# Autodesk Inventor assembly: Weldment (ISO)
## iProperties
Length Units: 11269
Angle Units: 11283
Time Units: 11279
Mass Units: 11290
Length Display Precision: 3
Angle Display Precision: 2
Part Number: Weldment (ISO)
Document SubType Name: Weldment
Created: 2002-06
Designer: smithga
Part Number: Ens_base_reduction
Created: 2008-04
Designer: plup
Material: Aluminum soudé-6061
Control State: 0
Master: False
Shininess: 64.0
Angle Units: 11279
Time Units: 11290
Mass Units: 11283
Compacted: True
DESIGNATION: Ensemble base réduction
Density: 0.0
Volumn: 0.0
Area: 0.0
PropertySet Name: Model Information
Author: plup
